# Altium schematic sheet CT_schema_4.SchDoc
size 529 x 503 mm
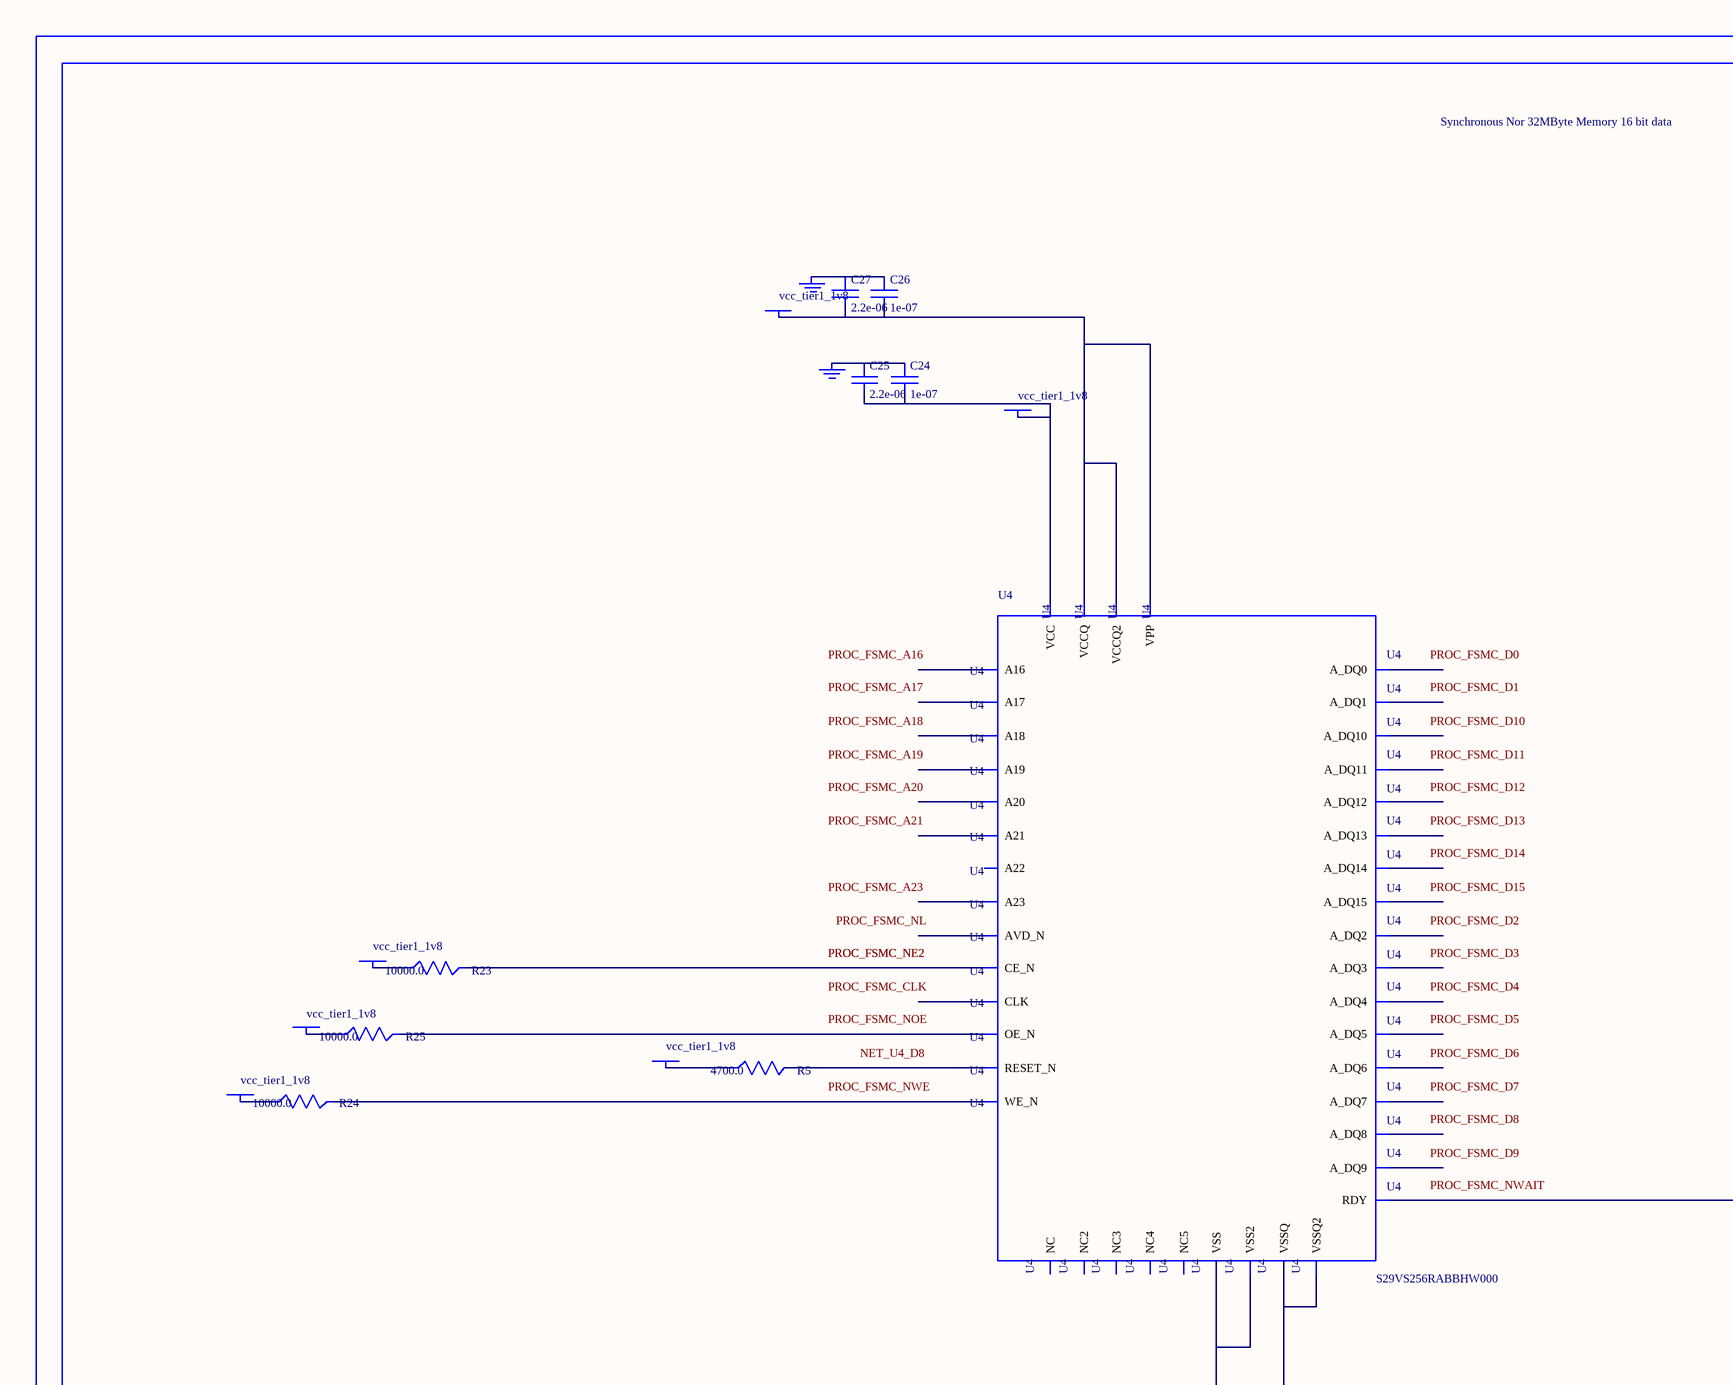
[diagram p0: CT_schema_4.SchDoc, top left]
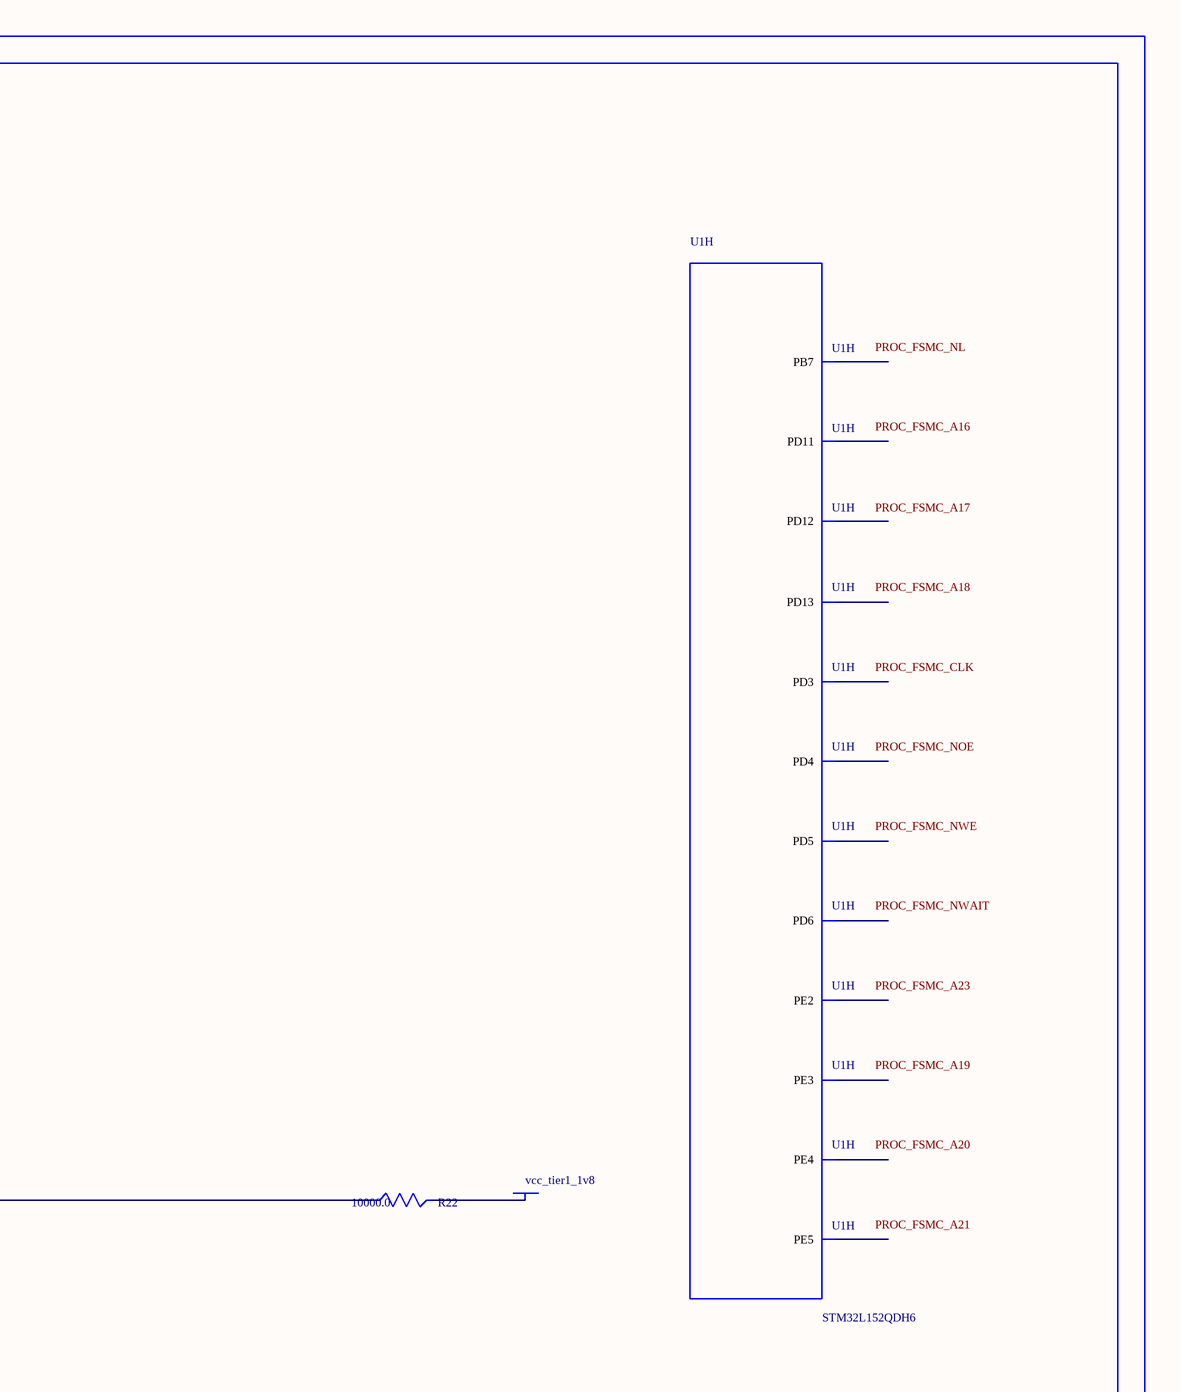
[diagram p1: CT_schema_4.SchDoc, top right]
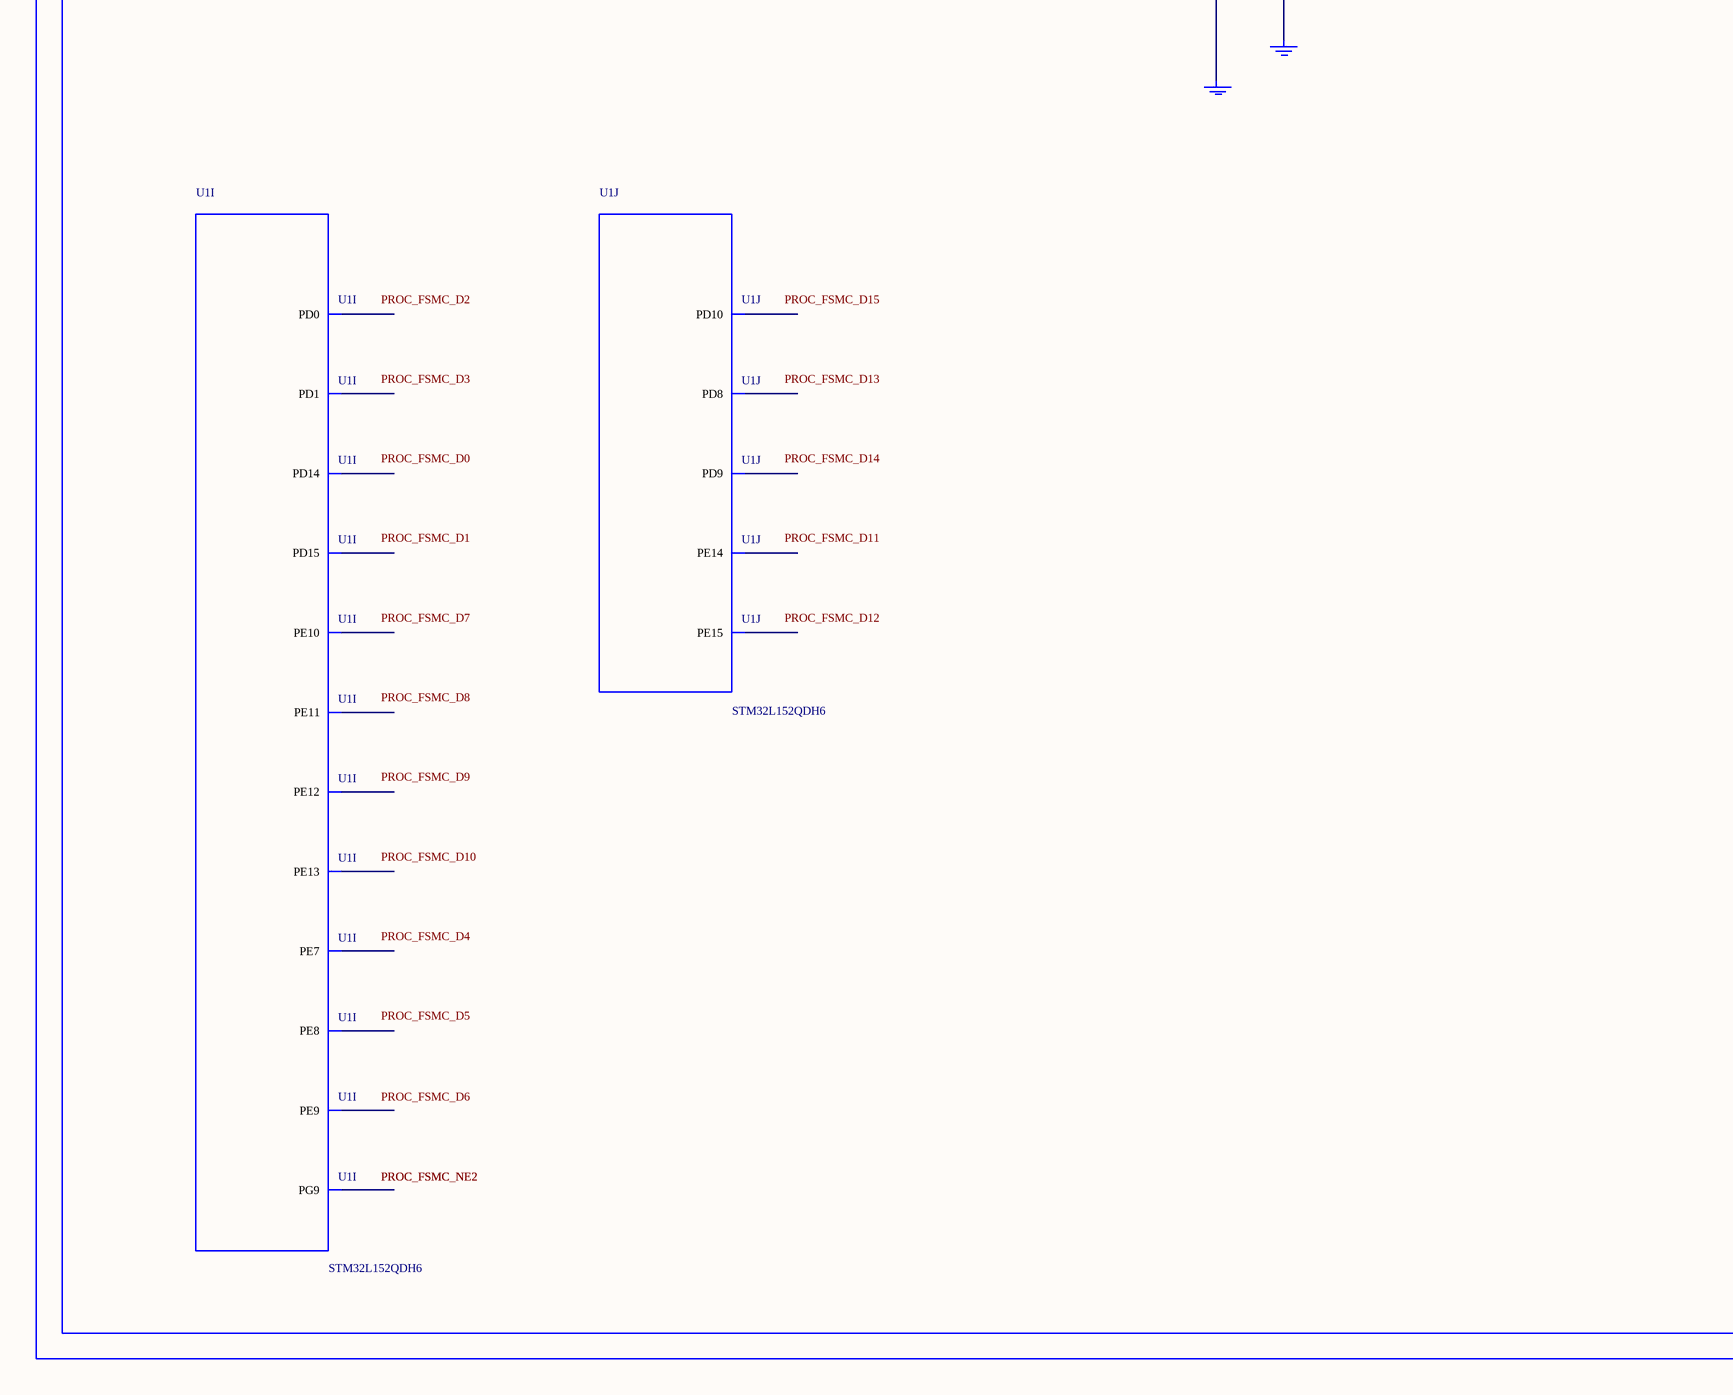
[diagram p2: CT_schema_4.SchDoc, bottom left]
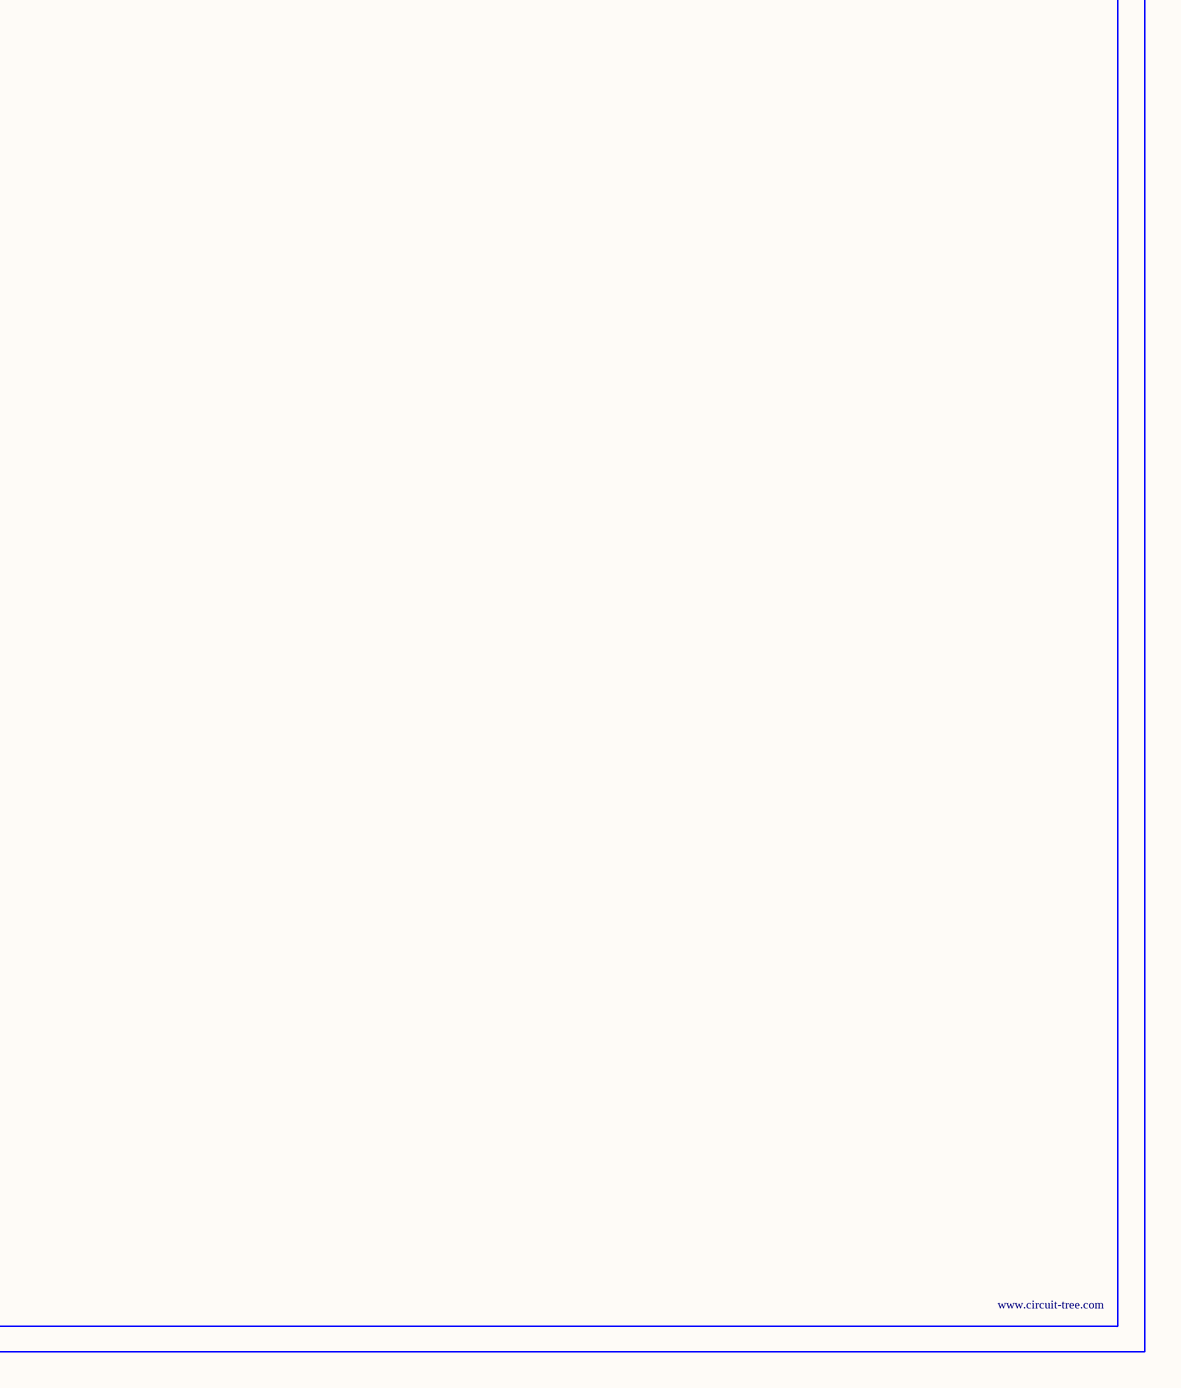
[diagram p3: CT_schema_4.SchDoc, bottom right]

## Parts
BORDER3  (no value)
C24  1e-07  [C0402]
C25  2.2e-06  [C0603]
C26  1e-07  [C0402]
C27  2.2e-06  [C0603]
GND_INSTANCE_3_0  (no value)
GND_INSTANCE_3_1  (no value)
GND_INSTANCE_3_2  (no value)
GND_INSTANCE_3_3  (no value)
POWER_INSTANCE_3_0  vcc_tier1_1v8
POWER_INSTANCE_3_1  vcc_tier1_1v8
POWER_INSTANCE_3_2  vcc_tier1_1v8
POWER_INSTANCE_3_3  vcc_tier1_1v8
POWER_INSTANCE_3_4  vcc_tier1_1v8
POWER_INSTANCE_3_5  vcc_tier1_1v8
POWER_INSTANCE_3_6  vcc_tier1_1v8
R5  4700.0  [R0603]
R22  10000.0  [R0603]
R23  10000.0  [R0603]
R24  10000.0  [R0603]
R25  10000.0  [R0603]
U1  STM32L152QDH6  [UFBGA132]  (parts H,I,J of 11)
U4  S29VS256RABBHW000  [S29VS256RABBHW000]

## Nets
NetC24_1: C24.1 C25.1 GND_INSTANCE_3_0.0(GND)
NetC24_2: C24.2 C25.2 POWER_INSTANCE_3_0.0(PWR) U4.C7(VCC)
NetC26_1: C26.1 C27.1 GND_INSTANCE_3_1.0(GND)
NetC26_2: C26.2 C27.2 POWER_INSTANCE_3_1.0(PWR) U4.C9(VPP) U4.D3(VCCQ) U4.F10(VCCQ2)
NetGND_INSTANCE_3_2_0: GND_INSTANCE_3_2.0(GND) U4.C5(VSS) U4.D12(VSS2)
NetGND_INSTANCE_3_3_0: GND_INSTANCE_3_3.0(GND) U4.E3(VSSQ) U4.F5(VSSQ2)
NetPOWER_INSTANCE_3_2_0: POWER_INSTANCE_3_2.0(PWR) R22.2
NetPOWER_INSTANCE_3_3_0: POWER_INSTANCE_3_3.0(PWR) R23.1
NetPOWER_INSTANCE_3_4_0: POWER_INSTANCE_3_4.0(PWR) R24.1
NetPOWER_INSTANCE_3_5_0: POWER_INSTANCE_3_5.0(PWR) R25.1
NetPOWER_INSTANCE_3_6_0: POWER_INSTANCE_3_6.0(PWR) R5.1
NetR5_2: R5.2 U4.D8(RESET_N)
NetR22_1: R22.1 U4.C3(RDY)
NetR23_2: R23.2 U4.D11(CE_N)
NetR24_2: R24.2 U4.C8(WE_N)
NetR25_2: R25.2 U4.E12(OE_N)

Not connected (* = marked no-connect by the designer): U1 A1(PE3) A6(PD5) B1(PE4) B2(PE2) B4(PB7) B6(PD6) B7(PD4) B8(PD3) B9(PD1) C2(PE5) C9(PD0) D9(PG9) H10(PD15) H11(PD14) H12(PD13) J10(PD12) J11(PD11) J12(PD10) K8(PD9) K9(PD8) L7(PE8) L8(PE10) L9(PE12) M7(PE7) M8(PE9) M9(PE11) M10(PE13) M11(PE14) M12(PE15); U4 A1(NC) A14(NC2) C4(A21) C6(CLK) C10(A19) C11(A17) C12(A22) D4(A16) D5(A20) D6(AVD_N) D7(A23) D9(NC3) D10(A18) E4(A_DQ8) E5(A_DQ9) E6(A_DQ2) E7(A_DQ3) E8(A_DQ12) E9(A_DQ13) E10(A_DQ6) E11(A_DQ7) F3(A_DQ0) F4(A_DQ1) F6(A_DQ10) F7(A_DQ11) F8(A_DQ4) F9(A_DQ5) F11(A_DQ14) F12(A_DQ15) H1(NC4) H14(NC5)

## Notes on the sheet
- Labels drawn without touching a wire or pin: NET_U4_D8, PROC_FSMC_A16, PROC_FSMC_A17, PROC_FSMC_A18, PROC_FSMC_A19, PROC_FSMC_A20, PROC_FSMC_A21, PROC_FSMC_A23, PROC_FSMC_CLK, PROC_FSMC_D0, PROC_FSMC_D1, PROC_FSMC_D2, PROC_FSMC_D3, PROC_FSMC_D4, PROC_FSMC_D5, PROC_FSMC_D6, PROC_FSMC_D7, PROC_FSMC_D8, PROC_FSMC_D9, PROC_FSMC_D10, PROC_FSMC_D11, PROC_FSMC_D12, PROC_FSMC_D13, PROC_FSMC_D14, PROC_FSMC_D15, PROC_FSMC_NL, PROC_FSMC_NOE, PROC_FSMC_NWAIT, PROC_FSMC_NWE

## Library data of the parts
BORDER3 = BORDER_PAGE3
C24 C26 = C0402C104K3RACTU
C25 C27 = C0603C225K8RACTU
GND_INSTANCE_3_0-GND_INSTANCE_3_3 = GND
POWER_INSTANCE_3_0-POWER_INSTANCE_3_6 = PWR
R5 = RC0603JR-074K7L
R22-R25 = RC0603JR-0710KL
